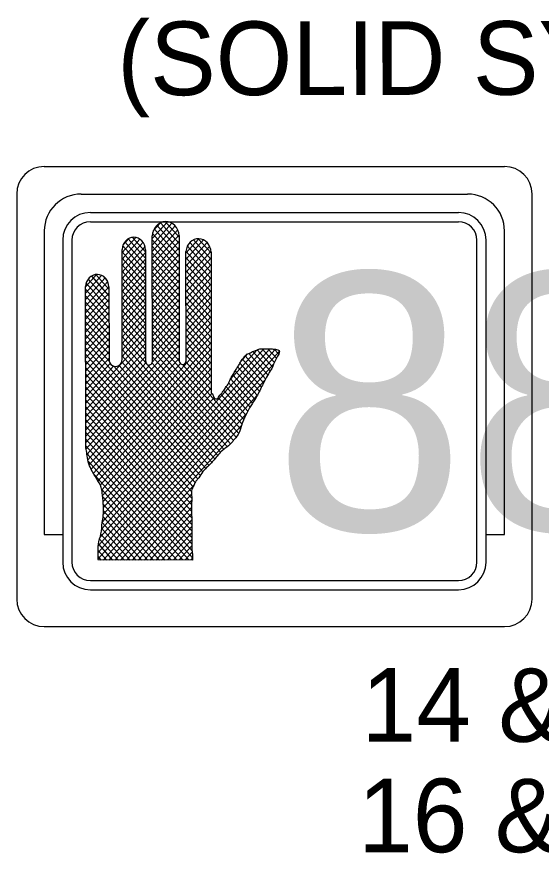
# Model space of a CAD drawing. Extents: x 660063 to 664816, y 641756 to 643817.
# Drawn here: x 661779.26 to 661807.76, y 642806.41 to 642851.86 of the extents above; entities that cross this region are included whole.
import ezdxf

# ---------------------------------------------------------------- set-up
doc = ezdxf.new("R2010")
doc.units = 0
doc.layers.add('T_Drafting', color=7, linetype='Continuous')
doc.layers.add('T_Notes', color=7, linetype='Continuous')

msp = doc.modelspace()

# ---------------------------------------------------------------- linework, layer by layer
at = {"layer": 'T_Drafting'}
for p, q in [((661780.764, 642843.722), (661805.764, 642843.722)), ((661779.264, 642842.222), (661779.264, 642820.222)), ((661782.764, 642842.222), (661803.764, 642842.222)), ((661807.264, 642820.222), (661807.264, 642842.222)), ((661783.264, 642841.222), (661803.264, 642841.222)), ((661783.264, 642840.722), (661803.264, 642840.722)), ((661786.629, 642839.806), (661787.451, 642840.719)), ((661786.629, 642839.453), (661787.694, 642840.636)), ((661786.682, 642840.219), (661787.083, 642840.665)), ((661787.076, 642840.661), (661788.092, 642839.532)), ((661787.337, 642840.725), (661788.092, 642839.886)), ((661787.803, 642840.56), (661787.945, 642840.403)), ((661780.764, 642840.222), (661780.764, 642823.722)), ((661786.629, 642839.1), (661787.878, 642840.488)), ((661786.63, 642838.747), (661788.013, 642840.283)), ((661786.734, 642840.334), (661788.093, 642838.824)), ((661786.88, 642840.526), (661788.093, 642839.178)), ((661805.764, 642823.722), (661805.764, 642840.222)), ((661781.764, 642839.722), (661781.764, 642822.222)), ((661782.264, 642839.722), (661782.264, 642822.222)), ((661784.99, 642839.047), (661785.728, 642839.866)), ((661784.991, 642838.693), (661785.96, 642839.77)), ((661785.048, 642839.464), (661785.359, 642839.809)), ((661785.318, 642839.786), (661786.264, 642838.735)), ((661785.56, 642839.871), (661786.264, 642839.089)), ((661785.985, 642839.752), (661786.154, 642839.564)), ((661786.636, 642833.122), (661786.628, 642839.949)), ((661786.629, 642839.744), (661788.094, 642838.116)), ((661786.63, 642838.394), (661788.088, 642840.013)), ((661786.631, 642838.041), (661788.092, 642839.665)), ((661786.644, 642840.081), (661788.094, 642838.47)), ((661788.092, 642839.968), (661788.099, 642833.19)), ((661788.459, 642839.011), (661789.164, 642839.795)), ((661788.459, 642838.658), (661789.421, 642839.727)), ((661788.866, 642839.733), (661789.82, 642838.673)), ((661789.128, 642839.796), (661789.82, 642839.027)), ((661804.264, 642822.222), (661804.264, 642839.722)), ((661804.764, 642822.222), (661804.764, 642839.722)), ((661784.997, 642833.249), (661784.99, 642839.214)), ((661784.991, 642838.34), (661786.128, 642839.604)), ((661784.992, 642837.987), (661786.237, 642839.371)), ((661785.026, 642839.404), (661786.265, 642838.027)), ((661785.142, 642839.628), (661786.264, 642838.381)), ((661786.263, 642839.2), (661786.27, 642833.154)), ((661786.629, 642839.39), (661788.094, 642837.762)), ((661786.631, 642837.687), (661788.093, 642839.311)), ((661788.46, 642838.305), (661789.611, 642839.584)), ((661788.46, 642837.952), (661789.746, 642839.381)), ((661788.536, 642839.393), (661789.821, 642837.965)), ((661788.674, 642839.593), (661789.821, 642838.319)), ((661784.99, 642839.089), (661786.265, 642837.673)), ((661784.991, 642838.735), (661786.266, 642837.319)), ((661784.992, 642837.634), (661786.264, 642839.047)), ((661786.63, 642839.036), (661788.095, 642837.408)), ((661786.631, 642837.334), (661788.093, 642838.958)), ((661788.466, 642833.157), (661788.459, 642839.105)), ((661788.459, 642838.771), (661789.822, 642837.257)), ((661788.46, 642839.123), (661789.821, 642837.611)), ((661788.46, 642837.599), (661789.817, 642839.106)), ((661788.461, 642837.246), (661789.82, 642838.756)), ((661789.82, 642839.058), (661789.829, 642831.401)), ((661784.991, 642838.381), (661786.266, 642836.965)), ((661784.992, 642837.281), (661786.264, 642838.694)), ((661784.993, 642836.928), (661786.264, 642838.341)), ((661786.63, 642838.682), (661788.095, 642837.054)), ((661786.63, 642838.328), (661788.096, 642836.7)), ((661786.632, 642836.981), (661788.093, 642838.605)), ((661788.46, 642838.417), (661789.822, 642836.903)), ((661788.461, 642836.893), (661789.82, 642838.403)), ((661783.002, 642837.191), (661783.598, 642837.853)), ((661783.561, 642837.849), (661784.276, 642837.055)), ((661784.992, 642838.027), (661786.266, 642836.611)), ((661784.993, 642836.575), (661786.265, 642837.988)), ((661786.631, 642837.974), (661788.096, 642836.346)), ((661786.632, 642836.628), (661788.094, 642838.252)), ((661786.633, 642836.275), (661788.094, 642837.899)), ((661788.46, 642838.063), (661789.822, 642836.549)), ((661788.462, 642836.54), (661789.821, 642838.05)), ((661783.003, 642836.838), (661783.873, 642837.805)), ((661783.003, 642836.485), (661784.069, 642837.669)), ((661783.003, 642836.132), (661784.206, 642837.468)), ((661783.035, 642837.373), (661784.277, 642835.993)), ((661783.149, 642837.6), (661784.276, 642836.347)), ((661783.322, 642837.761), (661784.276, 642836.701)), ((661783.964, 642837.755), (661784.187, 642837.508)), ((661784.992, 642837.673), (661786.267, 642836.257)), ((661784.994, 642836.222), (661786.265, 642837.635)), ((661786.631, 642837.62), (661788.096, 642835.992)), ((661786.633, 642835.922), (661788.095, 642837.546)), ((661788.46, 642837.709), (661789.823, 642836.195)), ((661788.462, 642836.186), (661789.821, 642837.697)), ((661783.011, 642828.95), (661783.002, 642837.193)), ((661783.002, 642837.056), (661784.277, 642835.639)), ((661783.004, 642835.778), (661784.275, 642837.191)), ((661784.275, 642837.179), (661784.28, 642833.248)), ((661784.992, 642837.319), (661786.267, 642835.903)), ((661784.993, 642836.965), (661786.268, 642835.549)), ((661784.994, 642835.869), (661786.266, 642837.281)), ((661784.994, 642835.515), (661786.266, 642836.928)), ((661786.632, 642837.266), (661788.097, 642835.638)), ((661786.633, 642835.569), (661788.095, 642837.193)), ((661788.461, 642837.355), (661789.823, 642835.841)), ((661788.461, 642837.001), (661789.823, 642835.487)), ((661788.462, 642835.833), (661789.822, 642837.343)), ((661788.463, 642835.48), (661789.822, 642836.99)), ((661783.003, 642836.702), (661784.278, 642835.285)), ((661783.004, 642835.425), (661784.276, 642836.838)), ((661783.004, 642835.072), (661784.276, 642836.485)), ((661784.993, 642836.611), (661786.268, 642835.195)), ((661784.995, 642835.162), (661786.266, 642836.575)), ((661786.632, 642836.912), (661788.097, 642835.284)), ((661786.632, 642836.558), (661788.098, 642834.93)), ((661786.634, 642835.216), (661788.095, 642836.84)), ((661786.634, 642834.863), (661788.096, 642836.487)), ((661788.462, 642836.647), (661789.824, 642835.133)), ((661788.463, 642835.127), (661789.822, 642836.637)), ((661783.003, 642836.348), (661784.278, 642834.931)), ((661783.005, 642834.719), (661784.277, 642836.132)), ((661784.994, 642836.257), (661786.268, 642834.841)), ((661784.995, 642834.809), (661786.267, 642836.222)), ((661786.633, 642836.204), (661788.098, 642834.576)), ((661786.635, 642834.509), (661788.096, 642836.133)), ((661788.462, 642836.293), (661789.824, 642834.779)), ((661788.464, 642834.774), (661789.823, 642836.284)), ((661783.003, 642835.994), (661784.278, 642834.577)), ((661783.004, 642835.64), (661784.279, 642834.223)), ((661783.005, 642834.366), (661784.277, 642835.779)), ((661784.994, 642835.903), (661786.269, 642834.487)), ((661784.996, 642834.456), (661786.267, 642835.869)), ((661786.633, 642835.85), (661788.098, 642834.222)), ((661786.635, 642834.156), (661788.097, 642835.78)), ((661788.462, 642835.939), (661789.825, 642834.425)), ((661788.463, 642835.585), (661789.825, 642834.071)), ((661788.464, 642834.421), (661789.823, 642835.931)), ((661788.464, 642834.068), (661789.823, 642835.578)), ((661783.004, 642835.286), (661784.279, 642833.869)), ((661783.006, 642834.013), (661784.277, 642835.426)), ((661784.994, 642835.549), (661786.269, 642834.133)), ((661784.995, 642835.196), (661786.27, 642833.779)), ((661784.996, 642834.103), (661786.268, 642835.516)), ((661784.996, 642833.75), (661786.268, 642835.163)), ((661786.634, 642835.496), (661788.099, 642833.868)), ((661786.634, 642835.142), (661788.099, 642833.514)), ((661786.635, 642833.803), (661788.097, 642835.427)), ((661788.463, 642835.231), (661789.825, 642833.717)), ((661788.465, 642833.715), (661789.824, 642835.225)), ((661783.005, 642834.932), (661784.28, 642833.515)), ((661783.006, 642833.66), (661784.278, 642835.073)), ((661783.006, 642833.307), (661784.278, 642834.72)), ((661784.995, 642834.842), (661786.27, 642833.425)), ((661784.997, 642833.397), (661786.268, 642834.81)), ((661786.632, 642833.093), (661788.098, 642834.721)), ((661786.634, 642834.788), (661788.094, 642833.166)), ((661786.636, 642833.45), (661788.097, 642835.074)), ((661788.464, 642834.877), (661789.826, 642833.363)), ((661788.465, 642833.362), (661789.824, 642834.871)), ((661783.005, 642834.578), (661784.291, 642833.149)), ((661783.005, 642834.224), (661789.383, 642827.138)), ((661783.007, 642832.953), (661784.279, 642834.367)), ((661783.009, 642830.835), (661786.269, 642834.457)), ((661783.023, 642828.729), (661788.098, 642834.368)), ((661783.304, 642827.273), (661789.824, 642834.518)), ((661784.996, 642834.488), (661786.286, 642833.054)), ((661786.635, 642834.434), (661791.329, 642829.219)), ((661788.464, 642834.523), (661789.826, 642833.009)), ((661783.006, 642833.87), (661789.235, 642826.948)), ((661783.007, 642832.6), (661784.279, 642834.013)), ((661783.009, 642830.482), (661786.269, 642834.103)), ((661783.01, 642830.128), (661786.27, 642833.75)), ((661783.034, 642828.388), (661788.099, 642834.015)), ((661783.427, 642827.057), (661789.825, 642834.165)), ((661783.552, 642826.842), (661789.825, 642833.812)), ((661783.697, 642823.114), (661793.302, 642833.786)), ((661783.802, 642823.584), (661793.014, 642833.819)), ((661783.873, 642824.016), (661792.695, 642833.819)), ((661784.996, 642834.134), (661790.342, 642828.193)), ((661784.996, 642833.78), (661790.185, 642828.014)), ((661786.635, 642834.08), (661791.189, 642829.02)), ((661788.464, 642834.169), (661789.826, 642832.655)), ((661788.465, 642833.815), (661789.827, 642832.302)), ((661790.866, 642832.14), (661792.322, 642833.758)), ((661792.331, 642833.762), (661793.162, 642832.838)), ((661792.598, 642833.819), (661793.264, 642833.079)), ((661792.916, 642833.819), (661793.377, 642833.306)), ((661793.257, 642833.793), (661793.488, 642833.537)), ((661783.006, 642833.516), (661789.101, 642826.744)), ((661783.008, 642832.247), (661784.279, 642833.66)), ((661783.008, 642831.894), (661784.28, 642833.307)), ((661783.01, 642829.775), (661786.27, 642833.397)), ((661783.083, 642828.089), (661788.099, 642833.662)), ((661783.132, 642827.79), (661788.099, 642833.308)), ((661783.676, 642826.626), (661789.826, 642833.459)), ((661783.687, 642822.749), (661793.533, 642833.689)), ((661784.997, 642833.426), (661790.029, 642827.834)), ((661786.636, 642833.726), (661791.039, 642828.833)), ((661786.636, 642833.372), (661790.882, 642828.654)), ((661788.465, 642833.461), (661789.827, 642831.948)), ((661791.468, 642833.162), (661791.81, 642833.542)), ((661791.674, 642833.431), (661792.79, 642832.191)), ((661791.871, 642833.566), (661792.912, 642832.409)), ((661792.096, 642833.67), (661793.04, 642832.62)), ((661783.007, 642833.162), (661788.958, 642826.55)), ((661783.008, 642831.541), (661784.343, 642833.024)), ((661783.009, 642831.188), (661784.524, 642832.871)), ((661783.011, 642829.422), (661786.284, 642833.059)), ((661783.011, 642829.069), (661786.494, 642832.939)), ((661783.197, 642827.507), (661788.157, 642833.019)), ((661783.687, 642822.396), (661793.226, 642832.995)), ((661783.797, 642826.407), (661789.826, 642833.106)), ((661784.548, 642832.863), (661789.542, 642827.314)), ((661784.825, 642832.909), (661789.705, 642827.487)), ((661784.971, 642833.1), (661789.867, 642827.66)), ((661786.378, 642832.952), (661790.514, 642828.356)), ((661786.615, 642833.042), (661790.702, 642828.501)), ((661788.272, 642832.968), (661791.422, 642829.468)), ((661788.458, 642833.115), (661789.827, 642831.594)), ((661791.392, 642833.038), (661792.566, 642831.733)), ((661791.523, 642833.245), (661792.678, 642831.962)), ((661783.007, 642832.808), (661788.846, 642826.32)), ((661783.007, 642832.454), (661788.762, 642826.06)), ((661783.892, 642826.158), (661789.826, 642832.752)), ((661783.927, 642825.844), (661789.827, 642832.399)), ((661791.007, 642832.404), (661792.207, 642831.071)), ((661791.131, 642832.62), (661792.329, 642831.289)), ((661791.271, 642832.818), (661792.448, 642831.51)), ((661783.008, 642832.1), (661788.773, 642825.694)), ((661783.952, 642822.337), (661792.751, 642832.113)), ((661783.957, 642825.524), (661789.827, 642832.046)), ((661790.781, 642831.948), (661791.947, 642830.653)), ((661790.887, 642832.184), (661792.078, 642830.861)), ((661783.008, 642831.746), (661788.759, 642825.356)), ((661783.976, 642825.192), (661789.827, 642831.693)), ((661790.509, 642831.543), (661791.706, 642830.213)), ((661790.643, 642831.748), (661791.825, 642830.435)), ((661783.008, 642831.392), (661788.76, 642825.002)), ((661783.009, 642831.038), (661788.776, 642824.631)), ((661783.918, 642824.42), (661789.99, 642831.166)), ((661783.974, 642824.835), (661789.873, 642831.39)), ((661784.271, 642822.337), (661792.332, 642831.294)), ((661790.212, 642831.166), (661791.504, 642829.731)), ((661790.361, 642831.355), (661791.598, 642829.979)), ((661783.009, 642830.684), (661788.777, 642824.275)), ((661783.01, 642830.33), (661788.778, 642823.921)), ((661784.59, 642822.338), (661791.75, 642830.294)), ((661783.01, 642829.976), (661788.778, 642823.567)), ((661783.01, 642829.622), (661788.78, 642823.211)), ((661783.011, 642829.268), (661788.795, 642822.842)), ((661784.908, 642822.338), (661791.467, 642829.626)), ((661783.013, 642828.912), (661788.814, 642822.466)), ((661783.026, 642828.545), (661788.607, 642822.343)), ((661783.075, 642828.136), (661788.289, 642822.343)), ((661783.147, 642827.702), (661787.971, 642822.342)), ((661783.459, 642827.003), (661787.653, 642822.342)), ((661783.889, 642826.171), (661787.336, 642822.341)), ((661785.227, 642822.339), (661788.9, 642826.419)), ((661783.935, 642825.766), (661787.018, 642822.341)), ((661785.545, 642822.339), (661788.769, 642825.921)), ((661785.864, 642822.339), (661788.767, 642825.565)), ((661783.967, 642825.377), (661786.7, 642822.341)), ((661786.183, 642822.34), (661788.757, 642825.201)), ((661783.959, 642824.68), (661786.064, 642822.34)), ((661783.979, 642825.01), (661786.382, 642822.34)), ((661786.501, 642822.34), (661788.765, 642824.856)), ((661783.912, 642824.378), (661785.747, 642822.339)), ((661786.82, 642822.341), (661788.777, 642824.516)), ((661783.842, 642823.749), (661785.111, 642822.338)), ((661783.877, 642824.063), (661785.429, 642822.339)), ((661787.138, 642822.341), (661788.777, 642824.162)), ((661787.457, 642822.342), (661788.778, 642823.809)), ((661780.764, 642823.722), (661781.764, 642823.722)), ((661783.767, 642823.478), (661784.793, 642822.338)), ((661787.775, 642822.342), (661788.778, 642823.456)), ((661804.764, 642823.722), (661805.764, 642823.722)), ((661783.688, 642822.859), (661784.158, 642822.337)), ((661783.702, 642823.196), (661784.475, 642822.337)), ((661788.094, 642822.343), (661788.783, 642823.108)), ((661783.687, 642822.506), (661783.84, 642822.337)), ((661788.413, 642822.343), (661788.798, 642822.771)), ((661788.731, 642822.343), (661788.815, 642822.436)), ((661783.713, 642822.336), (661783.687, 642822.368)), ((661788.792, 642822.344), (661783.713, 642822.336)), ((661788.816, 642822.338), (661788.792, 642822.344)), ((661783.264, 642821.222), (661803.264, 642821.222)), ((661783.264, 642820.722), (661803.264, 642820.722)), ((661780.764, 642818.722), (661805.764, 642818.722))]:
    msp.add_line(p, q, dxfattribs=at)
for centre, radius, start, end in [((661780.764, 642842.222), 1.5, 90, 180), ((661805.764, 642842.222), 1.5, 0, 90), ((661782.764, 642840.222), 2, 90, 180), ((661803.764, 642840.222), 2, 0, 90), ((661783.264, 642839.722), 1.5, 90, 180), ((661803.264, 642839.722), 1.5, 0, 90), ((661783.264, 642839.722), 1, 90, 180), ((661803.264, 642839.722), 1, 0, 90), ((661783.264, 642822.222), 1.5, 180, 270), ((661783.264, 642822.222), 1, 180, 270), ((661803.264, 642822.222), 1.5, 270, 0), ((661803.264, 642822.222), 1, 270, 0), ((661780.764, 642820.222), 1.5, 180, 270), ((661805.764, 642820.222), 1.5, 270, 0)]:
    msp.add_arc(centre, radius, start, end, dxfattribs=at)
for centre, major_axis, start_param, end_param in [((661787.361, 642839.911), (0, -0.814), 1.640121, 4.665593), ((661785.626, 642839.166), (0, -0.709), 1.618611, 4.644084), ((661789.138, 642839.038), (0, -0.758), 1.597842, 4.623315), ((661783.638, 642837.146), (0, -0.709), 1.618611, 4.644084), ((661784.638, 642833.249), (0, -0.398), 4.713646, 7.855239), ((661786.453, 642833.138), (0, -0.204), 4.633755, 7.775348), ((661788.28, 642833.175), (0, -0.207), 4.624552, 7.766145)]:
    msp.add_ellipse(centre, major_axis=major_axis, ratio=0.9, start_param=start_param, end_param=end_param, dxfattribs=at)
for points in [[(661789.828, 642831.402), (661789.879, 642831.388), (661789.948, 642831.233), (661790.037, 642831.114), (661790.089, 642831.095), (661790.176, 642831.114), (661790.23, 642831.195), (661790.388, 642831.389), (661790.511, 642831.547), (661790.582, 642831.663), (661790.652, 642831.761), (661790.775, 642831.937), (661790.845, 642832.094), (661790.95, 642832.309), (661791.021, 642832.427), (661791.144, 642832.641), (661791.283, 642832.838), (661791.389, 642833.033), (661791.511, 642833.228), (661791.618, 642833.365), (661791.775, 642833.523), (661791.968, 642833.602), (661792.074, 642833.661), (661792.233, 642833.718), (661792.373, 642833.779), (661792.585, 642833.819), (661792.761, 642833.819), (661792.989, 642833.819), (661793.201, 642833.8), (661793.447, 642833.761), (661793.517, 642833.72), (661793.533, 642833.663), (661793.43, 642833.409), (661793.359, 642833.271), (661793.29, 642833.133), (661793.219, 642832.978), (661793.183, 642832.88), (661793.043, 642832.624), (661792.834, 642832.273), (661792.552, 642831.706), (661792.2, 642831.058), (661791.92, 642830.608), (661791.761, 642830.315), (661791.622, 642830.039), (661791.539, 642829.822), (661791.496, 642829.711), (661791.339, 642829.239), (661791.095, 642828.906), (661790.901, 642828.671), (661790.62, 642828.435), (661790.444, 642828.298), (661789.987, 642827.788), (661789.584, 642827.359), (661789.32, 642827.064), (661789.091, 642826.73), (661788.977, 642826.585), (661788.881, 642826.38), (661788.775, 642826.182), (661788.776, 642825.752), (661788.759, 642825.366), (661788.759, 642825.012), (661788.777, 642824.544), (661788.778, 642824.094), (661788.778, 642823.37), (661788.797, 642822.788), (661788.814, 642822.572), (661788.815, 642822.414), (661788.815, 642822.339)], [(661783.687, 642822.368), (661783.687, 642822.682), (661783.703, 642823.209), (661783.843, 642823.758), (661783.913, 642824.384), (661783.965, 642824.736), (661783.965, 642825.421), (661783.911, 642825.988), (661783.857, 642826.281), (661783.594, 642826.769), (661783.312, 642827.259), (661783.153, 642827.67), (661783.081, 642828.1), (661783.028, 642828.432), (661783.028, 642828.646), (661783.011, 642828.95)]]:
    msp.add_spline(points, degree=3, dxfattribs=at)

# ---------------------------------------------------------------- texts
for s, height, p in [('(SOLID SYMBOL)', 4, (661784.731, 642847.59)), ('88', 14, (661793.229, 642823.943))]:
    msp.add_text(s, height=height, rotation=0.072, dxfattribs=at).set_placement(p)
at = {"layer": 'T_Notes'}
for s, p in [('14 & 15', (661797.997, 642812.465)), ('16 & 17', (661797.807, 642806.465))]:
    msp.add_text(s, height=4, dxfattribs=at).set_placement(p)

doc.saveas('drawing.dxf')
